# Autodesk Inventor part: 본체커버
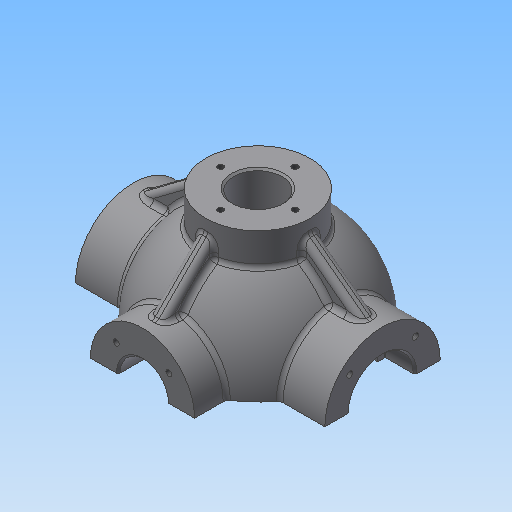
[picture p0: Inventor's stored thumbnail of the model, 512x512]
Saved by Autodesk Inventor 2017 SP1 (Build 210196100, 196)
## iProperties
Created: 2015-12
Part Number: 본체커버
Material: 일반
Document SubType Name: Modeling
Designer: mduedu
Density: 1 g/cm^3
Mass: 217.614 g
Surface Area: 460.056 cm^2
Volume: 217.614 cm^3
Appearance: 기본값
Author: mduedu
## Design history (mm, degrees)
sketch "스케치1"
  geometry: L1 (-53, 0)-(53, 0); A1 r 53 centre (0, 0) between (53, 0) and (-53, 0); 2 further points
  constraints: 2 coincident, 2 end point, 2 point on circle, 1 centre point, 1 horizontal, 1 midpoint
  dimensions: "d0" = 53 radius of A1
revolve "회전1" sketch "스케치1" stored, may be unused: angle "d2" = 90 deg
feature "쉘1" dims "d11" = 10
node "작업 평면1"
sketch "스케치2"
  geometry: C1 r 31 at (0, 0); 1 further point
  constraints: 1 centre point, 1 coincident
  dimensions: "d4" = 62 diameter of C1
extrude "돌출1" join sketch "스케치2" stored distance "d5" = 10; taper "d6" = 0 deg
node "작업 평면2"
sketch "스케치3"
  geometry: C1 r 28 at (0, 0); 1 further point
  constraints: 1 centre point, 1 coincident
  dimensions: "d8" = 56 diameter of C1
extrude "돌출2" join sketch "스케치3" stored distance "d9" = 10; taper "d10" = 0 deg
hole "구멍1" diameter "d14" = 35; stored, may be unused: countersink angle "d18" = 90 deg, drill point angle "d20" = 0 deg; dims "d12" = 10, "d13" = 10, "d15" = 6, "d16" = 4, "d17" = 2, "d19" = 16
hole "구멍2" diameter "d23" = 27; stored, may be unused: countersink angle "d27" = 90 deg, drill point angle "d29" = 0 deg; dims "d21" = 10, "d22" = 10, "d24" = 6, "d25" = 4, "d26" = 2, "d28" = 16
fillet "모깎기1" dims "d30" = 0.3
hole "구멍3" diameter "d33" = 26; stored, may be unused: countersink angle "d37" = 90 deg, drill point angle "d39" = 0 deg; dims "d31" = 10, "d32" = 10, "d34" = 6, "d35" = 4, "d36" = 2, "d38" = 16
chamfer "모따기1" distance "d40" = 1; stored, may be unused: second distance "d41" = 2, angle "d42" = 45 deg
sketch "스케치4"
  geometry: L1 (0, 0)-(0, -25); L2 (0, 0)-(-17.678, -17.678); A1 r 25 centre (0, 0) between (-17.678, -17.678) and (0, -25); 1 further point
  constraints: 4 end point, 2 point on circle, 1 centre point, 1 coincident, 1 vertical
  dimensions: "d43" = 50 diameter of A1; "d47" = 45 deg angle of L1 L2
hole "구멍4" sketch "스케치4" at (-17.678, -17.678) diameter "d49" = 3.242; stored, may be unused: countersink angle "d53" = 90 deg, drill point angle "d55" = 118 deg; dims "d50" = 11, "d51" = 4, "d52" = 2, "d54" = 13
sketch "스케치5"
  geometry: L1 (0, 0)-(0, -20); L2 (0, 0)-(-14.142, -14.142); A1 r 20 centre (0, 0) between (0, -20) and (-14.142, -14.142); 2 further points
  constraints: 4 end point, 2 coincident, 2 point on circle, 1 centre point, 1 vertical
  dimensions: "d59" = 40 diameter of A1; "d65" = 45 deg angle of L1 L2
hole "구멍5" sketch "스케치5" at (-14.142, -14.142) diameter "d67" = 3.242; stored, may be unused: countersink angle "d71" = 90 deg, drill point angle "d73" = 118 deg; dims "d68" = 8, "d69" = 4, "d70" = 2, "d72" = 10
node "작업 평면3"
sketch "스케치6"
  geometry: C1 r 65 at (0, 0); 1 further point
  constraints: 1 centre point, 1 coincident
  dimensions: "d78" = 130 diameter of C1
extrude "돌출3" join sketch "스케치6" distance "d80" = 10; taper "d81" = 0 deg
sketch "스케치7"
  geometry: C1 r 20 at (0, 0); 1 further point
  constraints: 1 centre point, 1 coincident
  dimensions: "d82" = 40 diameter of C1
extrude "돌출4" join sketch "스케치7" stored distance "d84" = 10; taper "d85" = 0 deg
sketch "스케치8"
  geometry: 2 further points
  constraints: 1 coincident
hole "구멍6" sketch "스케치8" at (0, 0) diameter "d86" = 20; stored, may be unused: countersink angle "d90" = 90 deg, drill point angle "d92" = 118 deg; dims "d87" = 7, "d88" = 40, "d89" = 5, "d91" = 10
fillet "모깎기2" dims "d93" = 0.3
sketch "스케치9"
  geometry: L1 (65, -75)-(-65, -75) reference; L2 (-45, -75)-(-38.245, -36.692); A1 r 53 centre (0, 0) between (42.988, 31) and (42.988, -31) reference; 1 further point
  constraints: 2 end point, 1 point on circle, 1 point on line
  dimensions: "d94" = 45 horizontal distance of L2.start point (0, 0); "d95" = 80 deg angle of L2 L1
feature "리브1" sketch "스케치9" dims "d96" = 1, "d97" = 8, "d98" = 0, "d99" = 0, "d100" = 1, "d101" = 1
sketch "스케치10"
  geometry: L1 (0, 0)-(0, -55); L2 (0, 0)-(-38.891, -38.891); A1 r 55 centre (0, 0) between (0, -55) and (-38.891, -38.891); 2 further points
  constraints: 4 end point, 2 coincident, 2 point on circle, 1 centre point, 1 vertical
  dimensions: "d105" = 110 diameter of A1; "d107" = 45 deg angle of L1 L2
hole "구멍7" sketch "스케치10" at (-38.891, -38.891) diameter "d109" = 10; stored, may be unused: countersink angle "d113" = 90 deg, drill point angle "d115" = 118 deg; dims "d110" = 7, "d111" = 40, "d112" = 5, "d114" = 10
fillet "모깎기3" dims "d120" = 3
fillet "모깎기4" dims "d121" = 3, "d122" = 3
fillet "모깎기5" dims "d123" = 3
fillet "모깎기6" dims "d124" = 3
sketch "스케치11"
  geometry: C1 r 5 at (-38.891, 38.891) reference; C2 r 5 at (38.891, 38.891) reference; C3 r 5 at (38.891, -38.891) reference; C4 r 5 at (-38.891, -38.891) reference; C5 r 20 at (0, 0) reference; C6 r 65 at (0, 0) reference; 1 further point
  constraints: 3 other
feature "엠보싱1" sketch "스케치11" dims "d125" = 0.5, "d126" = 0
sketch "스케치12"
  geometry: L1 (0, 100)-(0, -100); L2 (0, 100)-(-150, 100); L3 (-150, 100)-(-150, -100); L4 (-150, -100)-(0, -100); 2 further points
  constraints: 8 end point, 3 perpendicular, 1 coincident, 1 midpoint, 1 vertical
  dimensions: "d127" = 200 distance of L2.end L3.end; "d129" = 150 distance of L3.end L1.end
extrude "돌출5" cut sketch "스케치12" stored distance "d130" = 10; taper "d131" = 0 deg
sketch "스케치13"
  geometry: C1 r 7 at (0, -53); A1 r 53 centre (0, 0) between (-42.113, -32.179) and (42.113, -32.179) reference; 1 further point
  constraints: 1 centre point, 1 point on circle
  dimensions: "d132" = 14 diameter of C1
extrude "돌출6" join sketch "스케치13" distance "d133" = 5; taper "d134" = 0 deg
sketch "스케치14"
  geometry: C1 r 7 at (0, 0) reference; 1 further point
extrude "돌출7" cut sketch "스케치14" stored distance "d135" = 5; taper "d136" = 0 deg
sketch "스케치15"
  geometry: C1 r 2.25 at (0, 53); A1 r 7 centre (0, 53) between (6.965, 52.302) and (-6.965, 52.302) reference; 1 further point
  constraints: 1 centre point, 1 coincident
  dimensions: "d139" = 4.5 diameter of C1
extrude "돌출8" cut sketch "스케치15" stored distance "d141" = 5; taper "d142" = 0 deg
fillet "모깎기7" dims "d143" = 3
fillet "모깎기8" dims "d144" = 1
fillet "모깎기9" dims "d145" = 1
fillet "모깎기10" dims "d146" = 1
node "작업 평면4"
sketch "스케치16"
  geometry: C1 r 28 at (0, 0); 1 further point
  constraints: 1 centre point, 1 coincident
  dimensions: "d148" = 56 diameter of C1
extrude "돌출9" join sketch "스케치16" stored distance "d150" = 5; taper "d151" = 0 deg
hole "구멍8" diameter "d154" = 26; stored, may be unused: countersink angle "d158" = 90 deg, drill point angle "d160" = 118 deg; dims "d152" = 10, "d153" = 10, "d155" = 6, "d156" = 4, "d157" = 2, "d159" = 8
sketch "스케치17" dims "d161" = 40
  geometry: 3 further points
  constraints: 2 vertical alignment, 1 coincident, 2 other
hole "구멍9" sketch "스케치17" at (0, 20) diameter "d163" = 3.242; stored, may be unused: countersink angle "d167" = 90 deg, drill point angle "d169" = 118 deg; dims "d164" = 8, "d165" = 4, "d166" = 2, "d168" = 10
fillet "모깎기11" dims "d173" = 3
chamfer "모따기2" distance "d174" = 1; stored, may be unused: second distance "d175" = 2, angle "d176" = 45 deg
sketch "스케치18"
  geometry: L1 (28, 62)-(28, 46.637) reference; L2 (67, 31)-(44.497, 31) reference; L3 (28, 55)-(60, 31); L4 (-28, 62)-(28, 62) reference; L5 (67, 31)-(67, 0) reference; 1 further point
  constraints: 2 end point, 2 point on line
  dimensions: "d177" = 7 distance from line of L3.start L4; "d178" = 7 distance from line of L3.end L5
feature "리브2" sketch "스케치18" dims "d179" = 1, "d180" = 8, "d181" = 0, "d182" = 0, "d183" = 1, "d184" = 1
fillet "모깎기12" dims "d185" = 3
fillet "모깎기13" dims "d186" = 3
sketch "스케치19"
  geometry: L1 (62, 28)-(46.637, 28) reference; L2 (28, 62)-(28, 46.637) reference; L3 (55, 28)-(28, 55); L4 (0, 62)-(28, 62) reference; L5 (62, 28)-(62, -28) reference; 1 further point
  constraints: 2 end point, 2 point on line
  dimensions: "d187" = 7 distance from line of L3.end L4; "d188" = 7 distance from line of L3.start L5
feature "리브3" sketch "스케치19" dims "d189" = 1, "d190" = 8, "d191" = 0, "d192" = 0, "d193" = 1, "d194" = 1
fillet "모깎기14" dims "d195" = 3
fillet "모깎기15" dims "d196" = 3
node "솔리드1"
mirror "대칭1"
mirror "대칭2"
pattern_circular "원형 패턴1" dims angle "d57" = 360 deg
mirror "대칭3"
pattern_circular "원형 패턴2" dims angle "d75" = 360 deg
pattern_circular "원형 패턴3" dims angle "d103" = 360 deg
pattern_circular "원형 패턴4" dims angle "d118" = 360 deg
pattern_circular "원형 패턴5" dims angle "d171" = 360 deg
mirror "대칭4"
node "투영된 루프1"
other parameters: "d3" = 67, "d7" = 62, "d77" = -85, "d147" = 62
